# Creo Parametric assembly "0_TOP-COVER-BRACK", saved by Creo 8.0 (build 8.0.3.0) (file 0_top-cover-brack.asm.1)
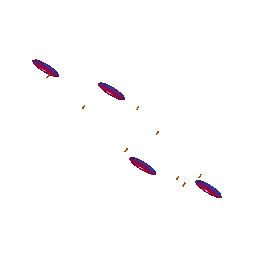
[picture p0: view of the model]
Units: millimeter Newton Second (mmNs); MM, TONNE, SECS

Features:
  1. component "2_GROMMET-1"
  2. component "2_GROMMET-1"
  3. component "2_GROMMET-1"
  4. component "2_GROMMET-1"
  5. component "2_GROMMET"
  6. component "2_GROMMET"
  7. component "2_GROMMET"
  8. component "2_GROMMET"
  9. component "3_SCAND-OFF-CREW"
  10. component "3_SCAND-OFF-CREW"
  11. component "3_SCAND-OFF-CREW"
  12. component "3_SCAND-OFF-CREW"
  13. component "3_SCAND-OFF-CREW"
  14. component "3_SCAND-OFF-CREW"
  15. component "3_SCAND-OFF-CREW"
  16. component "3_SCAND-OFF-CREW"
